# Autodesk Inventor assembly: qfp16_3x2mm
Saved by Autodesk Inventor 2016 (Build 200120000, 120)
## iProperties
Created: 2018-05
Part Number: qfp16_3x2mm
Document SubType Name: Assembly
Designer: Administrator
Title: qfp16_3x2mm v5
Author: Administrator
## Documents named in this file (3)
- c:\worker\convert-fusion-mar-2018\tmp\job-1\16\output\files\8c58ff39-88bb-4352-afd9-60265520bae5\qfp16_3x2mm v5.iam
- c:\worker\convert-fusion-mar-2018\tmp\job-1\16\output\files\8c58ff39-88bb-4352-afd9-60265520bae5\Component1.ipt
- c:\worker\convert-fusion-mar-2018\tmp\job-1\16\output\files\8c58ff39-88bb-4352-afd9-60265520bae5\lead.ipt
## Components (2 placed, 2 different names)
1. Component1:1
2. lead:1
